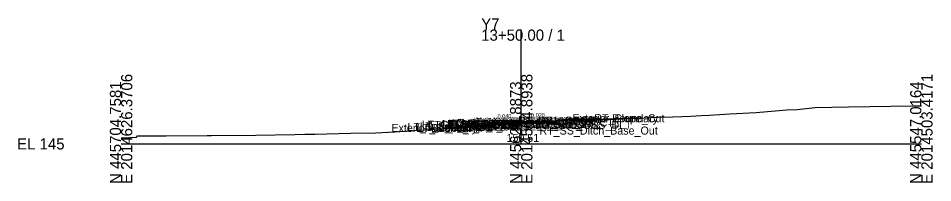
# Model space of a CAD drawing. Extents: x -26 to 203, y -10 to 7527.
# Drawn here: x -25.7 to 202.8, y 6990.3 to 7031.4 of the extents above; entities that cross this region are included whole.
import ezdxf

# ---------------------------------------------------------------- set-up
doc = ezdxf.new("R2010")
doc.units = 0
for name, color, linetype in [('Exist CMT Pavement', 7, 'Continuous'), ('Exist Cross Section Cell', 7, 'Continuous'), ('Exist XS Center Line Elevation Label', 7, 'Continuous'), ('Exist XS Ground Line', 7, 'Continuous'), ('Prop CMT Pvmt Course 1', 7, 'Continuous'), ('Prop CMT Pvmt Course 1 Wedge', 7, 'Continuous'), ('Prop CMT Pvmt Course 2', 7, 'Continuous'), ('Prop CMT Pvmt Course 2 Wedge', 7, 'Continuous'), ('Prop CMT Pvmt Course 3', 7, 'Continuous'), ('Prop CMT Pvmt Course 3 Wedge', 7, 'Continuous'), ('Prop CMT Pvmt Surface', 7, 'Continuous'), ('Prop CMT Pvmt Surface Shoulder', 7, 'Continuous'), ('Prop CMT Pvmt Wedge Surface 1', 7, 'Continuous'), ('Prop CMT Pvmt Wedge Surface 2', 7, 'Continuous'), ('Prop CMT Pvmt Wedge Surface 3', 7, 'Continuous'), ('Prop CMT Shld Paved Course 1', 7, 'Continuous'), ('Prop CMT Shld Paved Course 2', 7, 'Continuous'), ('Prop CMT Shld Paved Course 3', 7, 'Continuous'), ('Prop CMT Slope Grass', 7, 'Continuous'), ('Prop CMT Subgrade Earthwork', 7, 'Continuous'), ('Prop XS Earthwork Shape', 7, 'Continuous'), ('Prop XS SE Text', 7, 'Continuous'), ('Prop XS Side Slope Text', 7, 'Continuous'), ('Scratch_Level_0', 7, 'Continuous')]:
    doc.layers.add(name, color=color, linetype=linetype)

msp = doc.modelspace()

# ---------------------------------------------------------------- linework, layer by layer
at = {"layer": 'Exist CMT Pavement'}
msp.add_lwpolyline([(92.79, 7004.93), (93.8, 7005), (95.22, 7005.17), (95.53, 7005.22), (99.42, 7005.51), (100, 7005.51), (105.46, 7005.55), (107.51, 7005.58)], dxfattribs=at)
at = {"layer": 'Exist Cross Section Cell'}
for p, q in [((100, 7000), (100, 7028.57)), ((0, 7000), (100, 7000)), ((100, 7000), (200, 7000))]:
    msp.add_line(p, q, dxfattribs=at)
at = {"layer": 'Exist XS Ground Line'}
msp.add_lwpolyline([(0, 7001.5), (0.89, 7001.54), (3.81, 7001.71), (4.11, 7002), (11.25, 7002.05), (21.52, 7002.08), (22.61, 7002.09), (33.69, 7002.21), (43.41, 7002.36), (45.96, 7002.42), (48.4, 7002.47), (57.41, 7002.64), (63.64, 7002.76), (68.45, 7003.02), (83.33, 7003.98), (89.56, 7004.7), (93.8, 7005), (95.22, 7005.17), (95.53, 7005.22), (99.42, 7005.51), (100, 7005.51), (105.46, 7005.55), (108.02, 7005.59), (110.64, 7006.01), (112.02, 7006.16), (114.26, 7006.2), (115.63, 7006.23), (116.08, 7005.93), (118.22, 7005.98), (121.95, 7006.07), (130.74, 7006.51), (134.31, 7006.64), (137.87, 7006.77), (142.42, 7006.95), (144.99, 7007.07), (146.99, 7007.2), (152.12, 7007.52), (158.69, 7007.87), (159.67, 7007.93), (166.37, 7008.52), (168.99, 7008.6), (173.5, 7009.09), (181.78, 7009.27), (197.72, 7009.48), (200, 7009.52)], dxfattribs=at)
at = {"layer": 'Prop CMT Pvmt Course 1'}
for points in [[(100, 7005.59), (91.79, 7005.26)], [(91.79, 7005.26), (91.79, 7005.01)], [(91.79, 7005.01), (92.79, 7005.05)], [(92.79, 7005.18), (100, 7005.47)], [(92.79, 7005.05), (92.79, 7005.18)], [(100, 7005.59), (108.51, 7005.81)], [(107.51, 7005.66), (100, 7005.47)], [(100, 7005.34), (100, 7005.59)], [(100, 7005.34), (100, 7005.59)], [(100, 7005.47), (100, 7005.34), (100, 7005.34)], [(100, 7005.47), (100, 7005.34), (100, 7005.34)], [(107.51, 7005.54), (107.51, 7005.66)], [(108.51, 7005.56), (107.51, 7005.54)], [(108.51, 7005.81), (108.51, 7005.56)]]:
    msp.add_lwpolyline(points, dxfattribs=at)
at = {"layer": 'Prop CMT Pvmt Course 1 Wedge'}
for points in [[(100, 7005.47), (92.79, 7005.18)], [(100, 7005.47), (107.51, 7005.66)]]:
    msp.add_lwpolyline(points, dxfattribs=at)
at = {"layer": 'Prop CMT Pvmt Course 2'}
for points in [[(92.79, 7005.05), (91.79, 7005.01)], [(91.79, 7005.01), (91.79, 7004.76)], [(91.79, 7004.76), (92.79, 7004.8)], [(92.79, 7004.8), (92.79, 7005.05)], [(107.51, 7005.54), (108.51, 7005.56)], [(107.51, 7005.29), (107.51, 7005.54)], [(108.51, 7005.31), (107.51, 7005.29)], [(108.51, 7005.56), (108.51, 7005.31)]]:
    msp.add_lwpolyline(points, dxfattribs=at)
at = {"layer": 'Prop CMT Pvmt Course 2 Wedge'}
for points in [[(100, 7005.34), (92.79, 7005.05)], [(100, 7005.34), (107.51, 7005.54)]]:
    msp.add_lwpolyline(points, dxfattribs=at)
at = {"layer": 'Prop CMT Pvmt Course 3'}
for points in [[(92.79, 7004.8), (91.79, 7004.76)], [(91.79, 7004.76), (91.79, 7004.39)], [(92.79, 7004.43), (92.79, 7004.8)], [(107.51, 7005.29), (108.51, 7005.31)], [(107.51, 7004.91), (107.51, 7005.29)], [(108.51, 7004.94), (107.51, 7004.91)], [(108.51, 7005.31), (108.51, 7004.94)], [(91.79, 7004.39), (92.79, 7004.43)]]:
    msp.add_lwpolyline(points, dxfattribs=at)
at = {"layer": 'Prop CMT Pvmt Course 3 Wedge'}
for points in [[(100, 7005.09), (92.79, 7004.8)], [(100, 7005.09), (107.51, 7005.29)]]:
    msp.add_lwpolyline(points, dxfattribs=at)
at = {"layer": 'Prop CMT Pvmt Surface'}
for points in [[(100, 7005.59), (91.79, 7005.26)], [(100, 7005.59), (108.51, 7005.81)]]:
    msp.add_lwpolyline(points, dxfattribs=at)
at = {"layer": 'Prop CMT Pvmt Surface Shoulder'}
for points in [[(91.79, 7005.26), (91.79, 7005.26)], [(108.51, 7005.81), (108.51, 7005.81)]]:
    msp.add_lwpolyline(points, dxfattribs=at)
at = {"layer": 'Prop CMT Pvmt Wedge Surface 1'}
for points in [[(91.79, 7005.01), (91.79, 7005.26)], [(92.79, 7005.05), (91.79, 7005.01)], [(100, 7005.47), (92.79, 7005.18)], [(92.79, 7005.18), (92.79, 7005.05)], [(100, 7005.47), (107.51, 7005.66)], [(107.51, 7005.66), (107.51, 7005.54)], [(107.51, 7005.54), (108.51, 7005.56)], [(108.51, 7005.56), (108.51, 7005.81)]]:
    msp.add_lwpolyline(points, dxfattribs=at)
at = {"layer": 'Prop CMT Pvmt Wedge Surface 2'}
for points in [[(100, 7005.34), (91.79, 7005.01)], [(91.79, 7005.01), (91.79, 7005.26)], [(100, 7005.34), (108.51, 7005.56)], [(108.51, 7005.56), (108.51, 7005.81)]]:
    msp.add_lwpolyline(points, dxfattribs=at)
at = {"layer": 'Prop CMT Pvmt Wedge Surface 3'}
for points in [[(91.79, 7004.76), (91.79, 7005.26)], [(100, 7005.09), (91.79, 7004.76)], [(100, 7005.09), (108.51, 7005.31)], [(108.51, 7005.31), (108.51, 7005.81)]]:
    msp.add_lwpolyline(points, dxfattribs=at)
at = {"layer": 'Prop CMT Shld Paved Course 1'}
for points in [[(91.79, 7005.26), (91.54, 7005.01)], [(91.54, 7005.01), (91.79, 7005.01)], [(91.79, 7005.26), (91.79, 7005.26)], [(91.79, 7005.01), (91.79, 7005.26)], [(108.51, 7005.81), (108.51, 7005.81)], [(108.51, 7005.81), (108.77, 7005.56)], [(108.51, 7005.56), (108.51, 7005.81)], [(108.77, 7005.56), (108.51, 7005.56)]]:
    msp.add_lwpolyline(points, dxfattribs=at)
at = {"layer": 'Prop CMT Shld Paved Course 2'}
for points in [[(91.79, 7005.01), (91.54, 7005.01), (91.28, 7004.75)], [(91.28, 7004.75), (91.79, 7004.76)], [(91.79, 7004.76), (91.79, 7005.01)], [(108.51, 7005.56), (108.77, 7005.56), (109.02, 7005.3)], [(108.51, 7005.31), (108.51, 7005.56)], [(109.02, 7005.3), (108.51, 7005.31)]]:
    msp.add_lwpolyline(points, dxfattribs=at)
at = {"layer": 'Prop CMT Shld Paved Course 3'}
for points in [[(91.79, 7004.76), (91.28, 7004.75), (90.9, 7004.37)], [(91.79, 7004.39), (91.79, 7004.76)], [(108.51, 7004.94), (108.51, 7005.31)], [(108.51, 7005.31), (109.02, 7005.3), (109.4, 7004.92)], [(109.9, 7004.91), (108.51, 7004.94)], [(90.4, 7004.36), (91.79, 7004.39)]]:
    msp.add_lwpolyline(points, dxfattribs=at)
at = {"layer": 'Prop CMT Slope Grass'}
for points in [[(91.79, 7005.26), (85.79, 7004.78), (83.41, 7003.99)], [(108.51, 7005.81), (128.65, 7006.4)]]:
    msp.add_lwpolyline(points, dxfattribs=at)
at = {"layer": 'Prop CMT Subgrade Earthwork'}
msp.add_line((109.9, 7004.91), (115.79, 7006.03), dxfattribs=at)
for points in [[(92.79, 7004.43), (92.79, 7004.93)], [(107.51, 7004.91), (107.51, 7005.58)], [(107.51, 7004.91), (108.51, 7004.94)], [(108.51, 7004.94), (109.9, 7004.91)], [(90.4, 7004.36), (84.15, 7004.24)], [(91.79, 7004.39), (90.4, 7004.36)], [(92.79, 7004.43), (91.79, 7004.39)]]:
    msp.add_lwpolyline(points, dxfattribs=at)
at = {"layer": 'Prop XS Earthwork Shape'}
for points in [[(92.79, 7004.43), (91.79, 7004.39), (90.4, 7004.36), (85.84, 7004.27), (89.56, 7004.7), (92.79, 7004.93)], [(108.51, 7004.94), (109.9, 7004.91), (115.79, 7006.03), (115.94, 7006.03), (115.63, 7006.23), (112.02, 7006.16), (110.64, 7006.01), (109.1, 7005.76), (108.02, 7005.59), (107.51, 7005.58), (107.51, 7004.91)], [(115.94, 7006.03), (116.08, 7005.93), (121.95, 7006.07), (128.65, 7006.4)], [(85.84, 7004.27), (84.15, 7004.24), (83.41, 7003.99)]]:
    msp.add_lwpolyline(points, close=True, dxfattribs=at)

# ---------------------------------------------------------------- texts
at = {"layer": 'Exist Cross Section Cell'}
for s, p in [('Y7', (90, 7028.57)), ('13+50.00 / 1', (90, 7025.77)), ('EL 145', (-26, 6998.6))]:
    msp.add_text(s, height=2.8, dxfattribs=at).set_placement(p)
for s, p in [('E 2014626.3706', (2.8, 6990)), ('E 2014564.8938', (102.8, 6990)), ('E 2014503.4171', (202.8, 6990)), ('N 445704.7581', (0, 6990)), ('N 445625.8873', (100, 6990)), ('N 445547.0164', (200, 6990))]:
    msp.add_text(s, height=2.8, rotation=90, dxfattribs=at).set_placement(p)
at = {"layer": 'Exist XS Center Line Elevation Label'}
msp.add_text('150.51', height=2, dxfattribs=at).set_placement((96.32, 7000.51))
at = {"layer": 'Prop XS SE Text'}
for s, rotation, p in [('0.040', 2.2906, (94.11, 7006.36)), ('0.026', 1.4841, (102.49, 7006.66))]:
    msp.add_text(s, height=1, rotation=rotation, dxfattribs=at).set_placement(p)
at = {"layer": 'Prop XS Side Slope Text'}
msp.add_text('3:1', height=1, rotation=18.4332, dxfattribs=at).set_placement((83.61, 7004.85))
at = {"layer": 'Scratch_Level_0'}
for s, p in [('RT_PV1_OEOT', (99.2, 7004.81)), ('RT_PS1_OEOP', (99.27, 7004.81)), ('Exterior Boundary', (112.8, 7005.4)), ('RT_Slope_Cut', (118.25, 7005.4)), ('Exterior Boundary', (67.55, 7002.99)), ('LT_Sub_OSS_DLT', (71.55, 7003.24)), ('LT_Slope_Fill', (73.93, 7002.99)), ('LT_Sub_Trench_Out', (74.61, 7003.36)), ('LT_GS_OS_CTL', (75.16, 7003.78)), ('LT_PS3_Shelf_Out', (76.77, 7003.74)), ('LT_Sub Tie Out', (80.13, 7003.93)), ('LT_PV_OEEOP_EG', (80.34, 7003.93)), ('LT_PS3_OEOP', (81.52, 7003.75)), ('LT_PS2_OEOP', (81.77, 7004.01)), ('LT_Sub_OEOT', (81.87, 7003.39)), ('LT_PV2_OEOT', (81.97, 7004.01)), ('LT_PV3_OEOT', (81.97, 7003.76)), ('LT_Sub_OEEOP', (82.01, 7003.43)), ('LT_PV2_OEEOP', (82.1, 7004.05)), ('LT_PV3_OEEOP', (82.1, 7003.8)), ('LT_PV1_OEOT', (82.53, 7004.26)), ('LT_PS1_OEOP', (82.6, 7004.26)), ('LT_PV1_OEEOP', (82.67, 7004.18)), ('RT_PV_IEEOP_EG', (88.14, 7004.51)), ('LT_PV_IEEOP_EG', (88.19, 7004.51)), ('RT_PV2_IEEOP', (89.91, 7004.34)), ('RT_PV3_IEEOP', (89.91, 7004.09)), ('LT_PV2_IEEOP', (89.95, 7004.34)), ('LT_PV3_IEEOP', (89.95, 7004.09)), ('RT_PV1_IEEOP', (90.47, 7004.47)), ('LT_PV1_IEEOP', (90.52, 7004.47)), ('PV2_PGL', (93.91, 7004.34)), ('RT_Sub_Trench_Out', (94.06, 7003.91)), ('PV1_PGL', (94.47, 7004.59)), ('RT_Sub Tie Out', (94.8, 7004.58)), ('RT_PV_OEEOP_EG', (95.01, 7004.58)), ('RT_PS3_Shelf_Out', (95.46, 7004.29)), ('RT_Sub_OEEOP', (96.68, 7003.91)), ('RT_PV2_OEEOP', (96.77, 7004.54)), ('RT_PV3_OEEOP', (96.77, 7004.29)), ('RT_PV1_OEEOP', (97.34, 7004.66)), ('RT_Sub_OEOT', (98.54, 7003.94)), ('RT_PV2_OEOT', (98.64, 7004.56)), ('RT_PV3_OEOT', (98.64, 7004.31)), ('RT_PS2_OEOP', (98.95, 7004.56)), ('RT_PS3_OEOP', (99.21, 7004.3)), ('RT_GS_OS_CTL', (103.83, 7004.33)), ('RT_Sub_OSS_DLT', (104.1, 7003.77)), ('RT_SS_Ditch_Base_Out', (104.54, 7002.33))]:
    msp.add_text(s, height=2, dxfattribs=at).set_placement(p)

doc.saveas('drawing.dxf')
